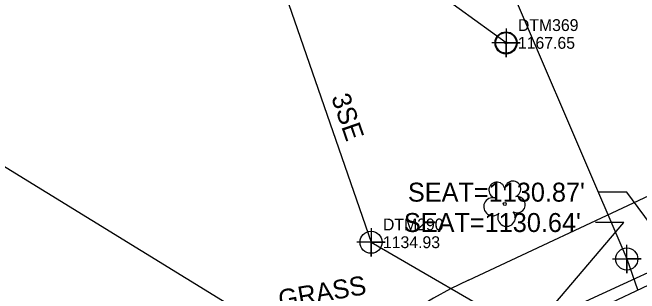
# Model space of a CAD drawing. Extents: x 1286007 to 1287145, y 857718 to 858514.
# Drawn here: x 1286447.6 to 1286580.3, y 858152 to 858211.3 of the extents above; entities that cross this region are included whole.
import ezdxf

# ---------------------------------------------------------------- set-up
doc = ezdxf.new("R2010")
doc.units = 0
for name, color, linetype in [('Default', 7, 'Continuous'), ('Exist Hydro Jurisdictional Stream or Body of Water', 7, 'Continuous'), ('Exist Hydro Stream or Body of Water Cogo Point CELL', 7, 'Continuous'), ('Exist Other Culture Fence Line', 7, 'Continuous'), ('Exist Other Culture Fence Line Cogo Elevation', 7, 'Continuous'), ('Exist Other Culture Fence Line Cogo Number', 7, 'Continuous'), ('Exist Other Culture Fence Line Cogo Point CELL', 7, 'Continuous'), ('Exist Other Culture Fence Line Text', 7, 'Continuous'), ('Exist Right of Way Line', 7, 'Continuous'), ('Exist Structure Major Bridge Seat Top Elevation', 7, 'Continuous'), ('Exist Structure Major Deck Tunnel Box Culvert', 7, 'Continuous'), ('Exist Utilities Other Located Object CELL', 7, 'Continuous'), ('Exist Utilities Other Located Object Leader', 7, 'Continuous'), ('Exist Utilities Power UG Cable Cogo Elevation', 7, 'Continuous'), ('Exist Utilities Power UG Cable Cogo Number', 7, 'Continuous'), ('Exist Utilities Power UG Cable Cogo Point CELL', 7, 'Continuous'), ('Exist Vegetation Tree CELL', 7, 'Continuous'), ('Exist Vegetation Tree Text', 7, 'Continuous')]:
    doc.layers.add(name, color=color, linetype=linetype)

msp = doc.modelspace()

# ---------------------------------------------------------------- linework, layer by layer
at = {"layer": 'Default'}
msp.add_line((1286521.31, 858132.59), (1286424.59, 858191.79), dxfattribs=at)
at = {"layer": 'Exist Hydro Jurisdictional Stream or Body of Water'}
msp.add_lwpolyline([(1286531.04, 858265.15), (1286547.36, 858229.81), (1286577.59, 858159.31), (1286579.86, 858152.89)], dxfattribs=at)
at = {"layer": 'Exist Hydro Stream or Body of Water Cogo Point CELL'}
msp.add_lwpolyline([(1286574.59, 858159.31), (1286580.59, 858159.31), (1286577.59, 858159.31), (1286577.59, 858156.31), (1286577.59, 858162.31)], dxfattribs=at)
msp.add_circle((1286577.59, 858159.31), 2.34, dxfattribs=at)
at = {"layer": 'Exist Other Culture Fence Line'}
msp.add_lwpolyline([(1286503.52, 858220.44), (1286523.48, 858162.85), (1286555.61, 858144.3), (1286656.76, 858190.72)], dxfattribs=at)
at = {"layer": 'Exist Other Culture Fence Line Cogo Point CELL'}
msp.add_lwpolyline([(1286523.48, 858165.85), (1286523.48, 858159.85), (1286523.48, 858162.85), (1286526.48, 858162.85), (1286520.48, 858162.85)], dxfattribs=at)
msp.add_circle((1286523.48, 858162.85), 2.34, dxfattribs=at)
at = {"layer": 'Exist Right of Way Line'}
msp.add_line((1286544.06, 858154.87), (1286633.12, 858196.48), dxfattribs=at)
msp.add_arc((1286585.13, 858066.99), 97, 115.044, 191.7253, dxfattribs=at)
at = {"layer": 'Exist Structure Major Bridge Seat Top Elevation'}
for points in [[(1286588.83, 858158.26), (1286577.62, 858173.42), (1286571.62, 858173.42)], [(1286557.33, 858143.97), (1286576.96, 858167.01), (1286570.96, 858167.01)]]:
    msp.add_lwpolyline(points, dxfattribs=at)
at = {"layer": 'Exist Structure Major Deck Tunnel Box Culvert'}
msp.add_line((1286657.3, 858188.97), (1286557.91, 858142.4), dxfattribs=at)
at = {"layer": 'Exist Utilities Other Located Object CELL'}
for radius in [2.18, 0.24]:
    msp.add_circle((1286552.04, 858204.95), radius, dxfattribs=at)
at = {"layer": 'Exist Utilities Other Located Object Leader'}
msp.add_line((1286552.04, 858204.95), (1286500.93, 858241.96), dxfattribs=at)
at = {"layer": 'Exist Utilities Power UG Cable Cogo Point CELL'}
msp.add_lwpolyline([(1286552.04, 858207.95), (1286552.04, 858201.95), (1286552.04, 858204.95), (1286555.04, 858204.95), (1286549.04, 858204.95)], dxfattribs=at)
msp.add_circle((1286552.04, 858204.95), 2.34, dxfattribs=at)
at = {"layer": 'Exist Vegetation Tree CELL'}
msp.add_line((1286551.76, 858170.94), (1286551.76, 858170.94), dxfattribs=at)
msp.add_circle((1286551.76, 858170.94), 0.326, dxfattribs=at)
for centre, radius, start, end in [((1286550.09, 858173.84), 1.7, 1.2822, 254.56), ((1286553.46, 858174.06), 1.69, 291.5671, 186.231), ((1286549.21, 858170.35), 1.9, 77.1011, 314.1999), ((1286554.37, 858170.78), 1.73, 242.6636, 99.3457), ((1286552.14, 858168.06), 1.86, 150.1651, 39.7134)]:
    msp.add_arc(centre, radius, start, end, dxfattribs=at)

# ---------------------------------------------------------------- texts
at = {"layer": 'Exist Other Culture Fence Line Cogo Elevation'}
msp.add_text('1134.93', height=2.5, dxfattribs=at).set_placement((1286525.98, 858161.6))
at = {"layer": 'Exist Other Culture Fence Line Cogo Number'}
msp.add_text('DTM290', height=2.5, dxfattribs=at).set_placement((1286525.98, 858165.35))
at = {"layer": 'Exist Other Culture Fence Line Text'}
msp.add_text('3SE', height=4, rotation=289.1163, dxfattribs=at).set_placement((1286514.99, 858193.46))
at = {"layer": 'Exist Structure Major Bridge Seat Top Elevation'}
for s, p in [("SEAT=1130.87'", (1286531.26, 858171.42)), ("SEAT=1130.64'", (1286530.41, 858165.01))]:
    msp.add_text(s, height=4, dxfattribs=at).set_placement(p)
at = {"layer": 'Exist Utilities Power UG Cable Cogo Elevation'}
msp.add_text('1167.65', height=2.5, dxfattribs=at).set_placement((1286554.54, 858203.7))
at = {"layer": 'Exist Utilities Power UG Cable Cogo Number'}
msp.add_text('DTM369', height=2.5, dxfattribs=at).set_placement((1286554.54, 858207.45))
at = {"layer": 'Exist Vegetation Tree Text'}
msp.add_text('GRASS', height=4, rotation=9.844, dxfattribs=at).set_placement((1286504.23, 858148.72))

doc.saveas('drawing.dxf')
